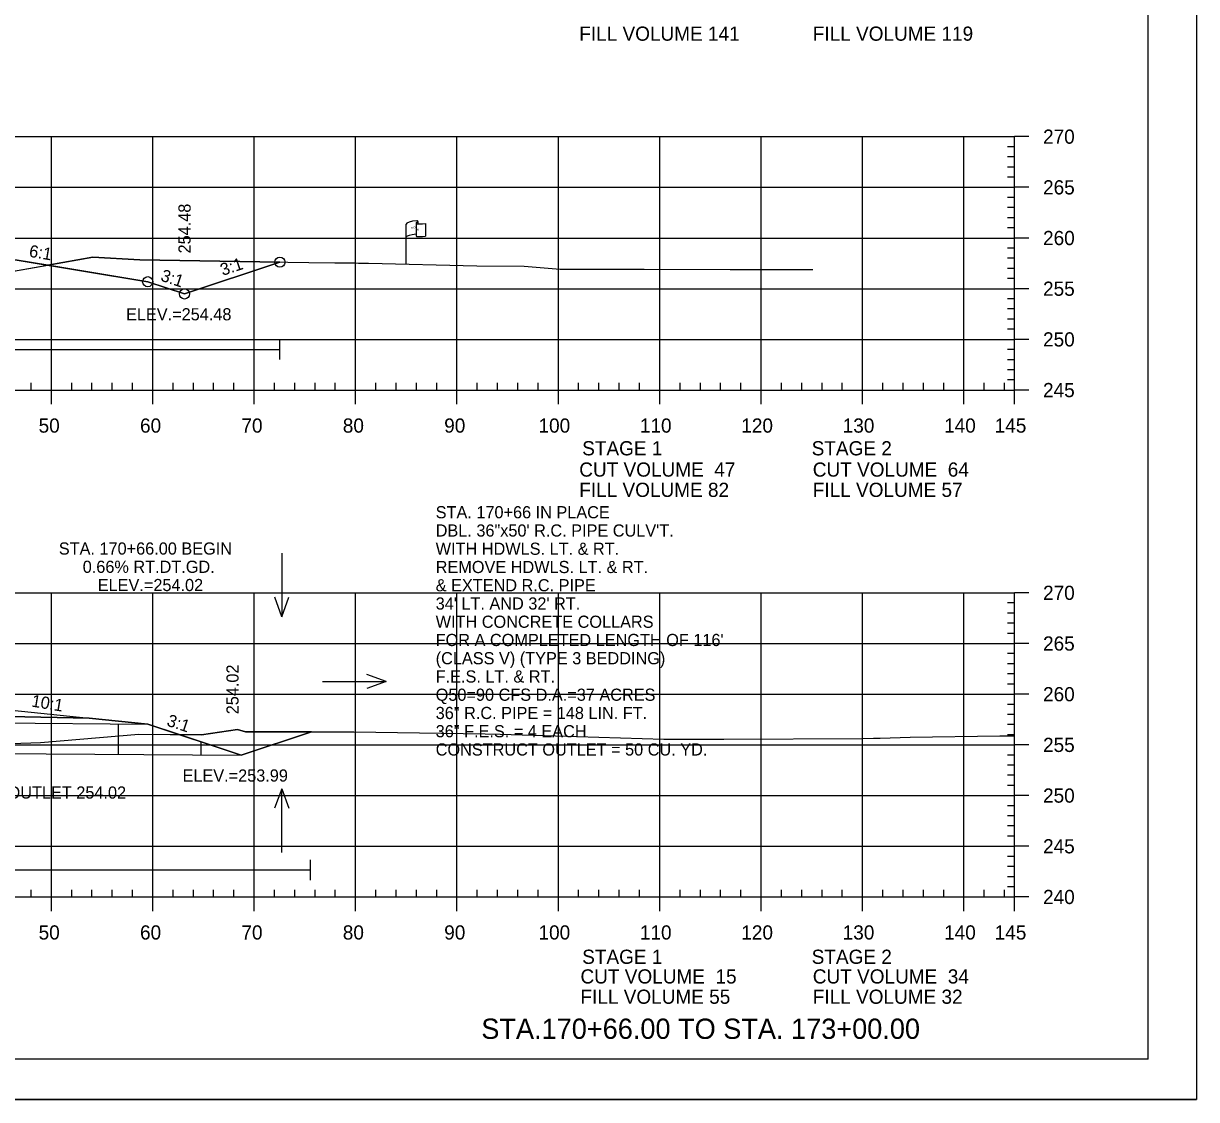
# Model space of a CAD drawing. Extents: x 1365647 to 1367999, y 387113 to 400173.
# Drawn here: x 1365941.3 to 1366057, y 387159.4 to 387265.5 of the extents above; entities that cross this region are included whole.
import ezdxf

# ---------------------------------------------------------------- set-up
doc = ezdxf.new("R2010")
doc.units = 0
for name, color, linetype in [('E_Existing ROW', 7, 'Continuous'), ('R_Alt Surface', 7, 'Continuous'), ('R_Axis', 7, 'Continuous'), ('R_Axis Annot', 7, 'Continuous'), ('R_Border', 7, 'Continuous'), ('R_Border Notes', 7, 'Continuous'), ('R_Contours', 7, 'Continuous'), ('R_Draft', 7, 'Continuous'), ('R_Exist Surface', 7, 'Continuous'), ('R_Fin Surface', 7, 'Continuous'), ('R_Fin Surface Annot', 7, 'Continuous'), ('R_Grid', 7, 'Continuous'), ('R_No Plot', 7, 'Continuous'), ('R_Proposed Const Limits', 7, 'Continuous'), ('R_Water', 7, 'Continuous'), ('R_Water Annot', 7, 'Continuous')]:
    doc.layers.add(name, color=color, linetype=linetype)

msp = doc.modelspace()

# ---------------------------------------------------------------- linework, layer by layer
at = {"layer": 'E_Existing ROW'}
for p, q in [((1365979.07, 387241.81), (1365979.07, 387245.76)), ((1365980.06, 387245.85), (1365980.06, 387245.84)), ((1365980.06, 387245.84), (1365980.06, 387244.61)), ((1365980.23, 387246.01), (1365980.23, 387245.77)), ((1365981, 387245.81), (1365981, 387244.57))]:
    msp.add_line(p, q, dxfattribs=at)
for centre, radius, start, end in [((1365980.14, 387245.85), 0.078, 88.6458, 274.2828), ((1365980.15, 387246.01), 0.0783, 263.0712, 93.9564), ((1365980.14, 387244.61), 0.0783, 180, 273.9564)]:
    msp.add_arc(centre, radius, start, end, dxfattribs=at)
for centre, major_axis, ratio, start_param, end_param in [((1365980.65, 387245.8), (-1.58, -0.04), 0.19887, 5.030368, 6.283185), ((1365981.36, 387245.91), (-1.23, -0.13), 0.052933, 0.159456, 1.268315), ((1365980.64, 387244.48), (-1.58, -0.04), 0.19887, 5.083035, 6.194897), ((1365981.36, 387244.67), (-1.23, -0.13), 0.052933, 0.159456, 1.268315)]:
    msp.add_ellipse(centre, major_axis=major_axis, ratio=ratio, start_param=start_param, end_param=end_param, dxfattribs=at)
at = {"layer": 'R_Alt Surface'}
msp.add_lwpolyline([(1365834.59, 387197.22), (1365862.59, 387197.47), (1365883.1, 387197.88), (1365883.1, 387199.17), (1365894.09, 387199.39), (1365906.38, 387199.14), (1365906.38, 387197.85), (1365925.59, 387197.47), (1365947.82, 387197.02)], dxfattribs=at)
at = {"layer": 'R_Axis'}
for p, q in [((1366039.09, 387253.38), (1366038.39, 387253.38)), ((1366039.09, 387229.38), (1366039.09, 387254.38)), ((1366040.49, 387254.38), (1366039.09, 387254.38)), ((1366039.09, 387252.38), (1366038.39, 387252.38)), ((1366039.09, 387251.38), (1366038.39, 387251.38)), ((1366039.09, 387250.38), (1366038.39, 387250.38)), ((1366040.49, 387249.38), (1366039.09, 387249.38)), ((1366039.09, 387248.38), (1366038.39, 387248.38)), ((1366039.09, 387247.38), (1366038.39, 387247.38)), ((1366039.09, 387246.38), (1366038.39, 387246.38)), ((1366039.09, 387245.38), (1366038.39, 387245.38)), ((1366040.49, 387244.38), (1366039.09, 387244.38)), ((1366039.09, 387243.38), (1366038.39, 387243.38)), ((1366039.09, 387242.38), (1366038.39, 387242.38)), ((1366039.09, 387241.38), (1366038.39, 387241.38)), ((1366039.09, 387240.38), (1366038.39, 387240.38)), ((1366039.09, 387238.38), (1366038.39, 387238.38)), ((1366040.49, 387239.38), (1366039.09, 387239.38)), ((1366039.09, 387237.38), (1366038.39, 387237.38)), ((1366039.09, 387236.38), (1366038.39, 387236.38)), ((1366039.09, 387235.38), (1366038.39, 387235.38)), ((1366040.49, 387234.38), (1366039.09, 387234.38)), ((1366039.09, 387233.38), (1366038.39, 387233.38)), ((1366039.09, 387232.38), (1366038.39, 387232.38)), ((1366039.09, 387231.38), (1366038.39, 387231.38)), ((1366039.09, 387230.38), (1366038.39, 387230.38)), ((1365749.09, 387229.38), (1366039.09, 387229.38)), ((1365942.09, 387229.38), (1365942.09, 387230.08)), ((1365944.09, 387227.98), (1365944.09, 387229.38)), ((1365946.09, 387229.38), (1365946.09, 387230.08)), ((1365948.09, 387229.38), (1365948.09, 387230.08)), ((1365950.09, 387229.38), (1365950.09, 387230.08)), ((1365952.09, 387229.38), (1365952.09, 387230.08)), ((1365954.09, 387227.98), (1365954.09, 387229.38)), ((1365956.09, 387229.38), (1365956.09, 387230.08)), ((1365958.09, 387229.38), (1365958.09, 387230.08)), ((1365960.09, 387229.38), (1365960.09, 387230.08)), ((1365962.09, 387229.38), (1365962.09, 387230.08)), ((1365964.09, 387227.98), (1365964.09, 387229.38)), ((1365966.09, 387229.38), (1365966.09, 387230.08)), ((1365968.09, 387229.38), (1365968.09, 387230.08)), ((1365970.09, 387229.38), (1365970.09, 387230.08)), ((1365972.09, 387229.38), (1365972.09, 387230.08)), ((1365974.09, 387227.98), (1365974.09, 387229.38)), ((1365976.09, 387229.38), (1365976.09, 387230.08)), ((1365978.09, 387229.38), (1365978.09, 387230.08)), ((1365980.09, 387229.38), (1365980.09, 387230.08)), ((1365982.09, 387229.38), (1365982.09, 387230.08)), ((1365984.09, 387227.98), (1365984.09, 387229.38)), ((1365986.09, 387229.38), (1365986.09, 387230.08)), ((1365988.09, 387229.38), (1365988.09, 387230.08)), ((1365990.09, 387229.38), (1365990.09, 387230.08)), ((1365992.09, 387229.38), (1365992.09, 387230.08)), ((1365994.09, 387227.98), (1365994.09, 387229.38)), ((1365996.09, 387229.38), (1365996.09, 387230.08)), ((1365998.09, 387229.38), (1365998.09, 387230.08)), ((1366000.09, 387229.38), (1366000.09, 387230.08)), ((1366002.09, 387229.38), (1366002.09, 387230.08)), ((1366004.09, 387227.98), (1366004.09, 387229.38)), ((1366006.09, 387229.38), (1366006.09, 387230.08)), ((1366008.09, 387229.38), (1366008.09, 387230.08)), ((1366010.09, 387229.38), (1366010.09, 387230.08)), ((1366012.09, 387229.38), (1366012.09, 387230.08)), ((1366014.09, 387227.98), (1366014.09, 387229.38)), ((1366016.09, 387229.38), (1366016.09, 387230.08)), ((1366018.09, 387229.38), (1366018.09, 387230.08)), ((1366020.09, 387229.38), (1366020.09, 387230.08)), ((1366022.09, 387229.38), (1366022.09, 387230.08)), ((1366024.09, 387227.98), (1366024.09, 387229.38)), ((1366026.09, 387229.38), (1366026.09, 387230.08)), ((1366028.09, 387229.38), (1366028.09, 387230.08)), ((1366030.09, 387229.38), (1366030.09, 387230.08)), ((1366032.09, 387229.38), (1366032.09, 387230.08)), ((1366034.09, 387227.98), (1366034.09, 387229.38)), ((1366036.09, 387229.38), (1366036.09, 387230.08)), ((1366038.09, 387229.38), (1366038.09, 387230.08)), ((1366039.09, 387227.98), (1366039.09, 387229.38)), ((1366040.49, 387229.38), (1366039.09, 387229.38)), ((1366039.09, 387208.38), (1366038.39, 387208.38)), ((1366039.09, 387179.38), (1366039.09, 387209.38)), ((1366040.49, 387209.38), (1366039.09, 387209.38)), ((1366039.09, 387207.38), (1366038.39, 387207.38)), ((1366039.09, 387206.38), (1366038.39, 387206.38)), ((1366039.09, 387205.38), (1366038.39, 387205.38)), ((1366040.49, 387204.38), (1366039.09, 387204.38)), ((1366039.09, 387203.38), (1366038.39, 387203.38)), ((1366039.09, 387202.38), (1366038.39, 387202.38)), ((1366039.09, 387201.38), (1366038.39, 387201.38)), ((1366039.09, 387200.38), (1366038.39, 387200.38)), ((1366040.49, 387199.38), (1366039.09, 387199.38)), ((1366039.09, 387198.38), (1366038.39, 387198.38)), ((1366039.09, 387197.38), (1366038.39, 387197.38)), ((1366039.09, 387196.38), (1366038.39, 387196.38)), ((1366039.09, 387195.38), (1366038.39, 387195.38)), ((1366040.49, 387194.38), (1366039.09, 387194.38)), ((1366039.09, 387193.38), (1366038.39, 387193.38)), ((1366039.09, 387192.38), (1366038.39, 387192.38)), ((1366039.09, 387191.38), (1366038.39, 387191.38)), ((1366039.09, 387190.38), (1366038.39, 387190.38)), ((1366040.49, 387189.38), (1366039.09, 387189.38)), ((1366039.09, 387188.38), (1366038.39, 387188.38)), ((1366039.09, 387187.38), (1366038.39, 387187.38)), ((1366039.09, 387186.38), (1366038.39, 387186.38)), ((1366039.09, 387185.38), (1366038.39, 387185.38)), ((1366040.49, 387184.38), (1366039.09, 387184.38)), ((1366039.09, 387183.38), (1366038.39, 387183.38)), ((1366039.09, 387182.38), (1366038.39, 387182.38)), ((1366039.09, 387181.38), (1366038.39, 387181.38)), ((1365749.09, 387179.38), (1366039.09, 387179.38)), ((1365942.09, 387179.38), (1365942.09, 387180.08)), ((1365944.09, 387177.98), (1365944.09, 387179.38)), ((1365946.09, 387179.38), (1365946.09, 387180.08)), ((1365948.09, 387179.38), (1365948.09, 387180.08)), ((1365950.09, 387179.38), (1365950.09, 387180.08)), ((1365952.09, 387179.38), (1365952.09, 387180.08)), ((1365954.09, 387177.98), (1365954.09, 387179.38)), ((1365956.09, 387179.38), (1365956.09, 387180.08)), ((1365958.09, 387179.38), (1365958.09, 387180.08)), ((1365960.09, 387179.38), (1365960.09, 387180.08)), ((1365962.09, 387179.38), (1365962.09, 387180.08)), ((1365964.09, 387177.98), (1365964.09, 387179.38)), ((1365966.09, 387179.38), (1365966.09, 387180.08)), ((1365968.09, 387179.38), (1365968.09, 387180.08)), ((1365970.09, 387179.38), (1365970.09, 387180.08)), ((1365972.09, 387179.38), (1365972.09, 387180.08)), ((1365974.09, 387177.98), (1365974.09, 387179.38)), ((1365976.09, 387179.38), (1365976.09, 387180.08)), ((1365978.09, 387179.38), (1365978.09, 387180.08)), ((1365980.09, 387179.38), (1365980.09, 387180.08)), ((1365982.09, 387179.38), (1365982.09, 387180.08)), ((1365984.09, 387177.98), (1365984.09, 387179.38)), ((1365986.09, 387179.38), (1365986.09, 387180.08)), ((1365988.09, 387179.38), (1365988.09, 387180.08)), ((1365990.09, 387179.38), (1365990.09, 387180.08)), ((1365992.09, 387179.38), (1365992.09, 387180.08)), ((1365994.09, 387177.98), (1365994.09, 387179.38)), ((1365996.09, 387179.38), (1365996.09, 387180.08)), ((1365998.09, 387179.38), (1365998.09, 387180.08)), ((1366000.09, 387179.38), (1366000.09, 387180.08)), ((1366002.09, 387179.38), (1366002.09, 387180.08)), ((1366004.09, 387177.98), (1366004.09, 387179.38)), ((1366006.09, 387179.38), (1366006.09, 387180.08)), ((1366008.09, 387179.38), (1366008.09, 387180.08)), ((1366010.09, 387179.38), (1366010.09, 387180.08)), ((1366012.09, 387179.38), (1366012.09, 387180.08)), ((1366014.09, 387177.98), (1366014.09, 387179.38)), ((1366016.09, 387179.38), (1366016.09, 387180.08)), ((1366018.09, 387179.38), (1366018.09, 387180.08)), ((1366020.09, 387179.38), (1366020.09, 387180.08)), ((1366022.09, 387179.38), (1366022.09, 387180.08)), ((1366024.09, 387177.98), (1366024.09, 387179.38)), ((1366026.09, 387179.38), (1366026.09, 387180.08)), ((1366028.09, 387179.38), (1366028.09, 387180.08)), ((1366030.09, 387179.38), (1366030.09, 387180.08)), ((1366032.09, 387179.38), (1366032.09, 387180.08)), ((1366034.09, 387177.98), (1366034.09, 387179.38)), ((1366036.09, 387179.38), (1366036.09, 387180.08)), ((1366038.09, 387179.38), (1366038.09, 387180.08)), ((1366039.09, 387180.38), (1366038.39, 387180.38)), ((1366039.09, 387177.98), (1366039.09, 387179.38)), ((1366040.49, 387179.38), (1366039.09, 387179.38))]:
    msp.add_line(p, q, dxfattribs=at)
at = {"layer": 'R_Border'}
for q in [(1366052.27, 387368.84), (1365736.09, 387163.38)]:
    msp.add_line((1366052.27, 387163.38), q, dxfattribs=at)
at = {"layer": 'R_Contours'}
for p, q in [((1365943.74, 387241.71), (1365953.59, 387240.07)), ((1365962.79, 387193.36), (1365969.74, 387195.68)), ((1365956.7, 387195.4), (1365962.79, 387193.36))]:
    msp.add_line(p, q, dxfattribs=at)
for points in [[(1365918.26, 387242.66), (1365921.8, 387241.75), (1365928.13, 387240.33), (1365930.06, 387239.89), (1365930.55, 387239.93), (1365936.05, 387240.24), (1365937.69, 387240.65), (1365943.74, 387241.71), (1365940.72, 387242.21), (1365925.59, 387242.52)], [(1365943.74, 387241.71), (1365948.16, 387242.49), (1365952.81, 387242.23), (1365966.63, 387242), (1365957.22, 387238.86), (1365953.59, 387240.07)], [(1365917.65, 387197.63), (1365918.43, 387197.36), (1365918.9, 387197.26), (1365919.65, 387197.14), (1365920.43, 387194.63), (1365920.89, 387193.95), (1365932.66, 387194.31), (1365937.2, 387194.43), (1365943.03, 387194.63), (1365952.7, 387195.43), (1365956.7, 387195.4), (1365953.59, 387196.43), (1365947.82, 387197.02), (1365925.59, 387197.47)], [(1365956.7, 387195.4), (1365958.9, 387195.38), (1365962.46, 387195.91), (1365963.22, 387195.68), (1365969.74, 387195.68), (1365962.79, 387193.36)]]:
    msp.add_lwpolyline(points, close=True, dxfattribs=at)
for points in [[(1365966.63, 387242), (1365952.81, 387242.23), (1365948.16, 387242.49), (1365943.74, 387241.71)], [(1365953.59, 387240.07), (1365957.22, 387238.86), (1365966.63, 387242)], [(1365969.74, 387195.68), (1365963.22, 387195.68), (1365962.46, 387195.91), (1365958.9, 387195.38), (1365956.7, 387195.4)]]:
    msp.add_lwpolyline(points, dxfattribs=at)
at = {"layer": 'R_Exist Surface'}
for points in [[(1365937.69, 387240.65), (1365948.16, 387242.49), (1365952.81, 387242.23), (1365969.49, 387241.95), (1365972.04, 387241.93), (1365973.98, 387241.93), (1365974.38, 387241.89), (1365975.37, 387241.89), (1365986.04, 387241.64), (1365990.71, 387241.61), (1365994.28, 387241.3), (1366002.55, 387241.32), (1366011.04, 387241.27), (1366019.17, 387241.29)], [(1365937.2, 387194.43), (1365943.03, 387194.63), (1365952.7, 387195.43), (1365958.9, 387195.38), (1365962.46, 387195.91), (1365963.22, 387195.68), (1365970.46, 387195.68), (1365973.92, 387195.68), (1365986.88, 387195.46), (1365988.34, 387195.45), (1365993.79, 387195.27), (1366004.5, 387194.93), (1366010.41, 387194.95), (1366024.12, 387195.02), (1366025.16, 387195.03), (1366025.83, 387195.05), (1366028.8, 387195.14), (1366037.64, 387195.28), (1366039.09, 387195.29)]]:
    msp.add_lwpolyline(points, dxfattribs=at)
at = {"layer": 'R_Fin Surface'}
for points in [[(1365823.26, 387242.8), (1365833.02, 387239.54), (1365834.59, 387240.07), (1365847.47, 387242.21), (1365856.59, 387243.73), (1365862.59, 387243.97), (1365864.59, 387244.01), (1365894.09, 387244.6), (1365923.59, 387244.01), (1365925.59, 387243.97), (1365931.59, 387243.73), (1365940.72, 387242.21), (1365953.59, 387240.07), (1365957.22, 387238.86), (1365966.63, 387242)], [(1365815.46, 387197.88), (1365826.02, 387194.36), (1365830.31, 387195.79), (1365834.59, 387197.22), (1365856.59, 387198.69), (1365862.59, 387198.93), (1365864.59, 387198.97), (1365894.09, 387199.56), (1365923.59, 387198.97), (1365925.59, 387198.93), (1365931.59, 387198.69), (1365947.82, 387197.02), (1365953.59, 387196.43), (1365962.79, 387193.36), (1365969.74, 387195.68)]]:
    msp.add_lwpolyline(points, dxfattribs=at)
at = {"layer": 'R_Grid'}
for p, q in [((1365749.09, 387254.38), (1366039.09, 387254.38)), ((1365944.09, 387229.38), (1365944.09, 387254.38)), ((1365954.09, 387229.38), (1365954.09, 387254.38)), ((1365964.09, 387229.38), (1365964.09, 387254.38)), ((1365974.09, 387229.38), (1365974.09, 387254.38)), ((1365984.09, 387229.38), (1365984.09, 387254.38)), ((1365994.09, 387229.38), (1365994.09, 387254.38)), ((1366004.09, 387229.38), (1366004.09, 387254.38)), ((1366014.09, 387229.38), (1366014.09, 387254.38)), ((1366024.09, 387229.38), (1366024.09, 387254.38)), ((1366034.09, 387229.38), (1366034.09, 387254.38)), ((1366039.09, 387229.38), (1366039.09, 387254.38)), ((1365749.09, 387249.38), (1366039.09, 387249.38)), ((1365749.09, 387244.38), (1366039.09, 387244.38)), ((1365749.09, 387239.38), (1366039.09, 387239.38)), ((1365749.09, 387234.38), (1366039.09, 387234.38)), ((1365749.09, 387229.38), (1366039.09, 387229.38)), ((1365749.09, 387209.38), (1366039.09, 387209.38)), ((1365944.09, 387179.38), (1365944.09, 387209.38)), ((1365954.09, 387179.38), (1365954.09, 387209.38)), ((1365964.09, 387179.38), (1365964.09, 387209.38)), ((1365974.09, 387179.38), (1365974.09, 387209.38)), ((1365984.09, 387179.38), (1365984.09, 387209.38)), ((1365994.09, 387179.38), (1365994.09, 387209.38)), ((1366004.09, 387179.38), (1366004.09, 387209.38)), ((1366014.09, 387179.38), (1366014.09, 387209.38)), ((1366024.09, 387179.38), (1366024.09, 387209.38)), ((1366034.09, 387179.38), (1366034.09, 387209.38)), ((1366039.09, 387179.38), (1366039.09, 387209.38)), ((1365749.09, 387204.38), (1366039.09, 387204.38)), ((1365749.09, 387199.38), (1366039.09, 387199.38)), ((1365749.09, 387194.38), (1366039.09, 387194.38)), ((1365749.09, 387189.38), (1366039.09, 387189.38)), ((1365749.09, 387184.38), (1366039.09, 387184.38)), ((1365749.09, 387179.38), (1366039.09, 387179.38))]:
    msp.add_line(p, q, dxfattribs=at)
at = {"layer": 'R_No Plot'}
msp.add_line((1365723.69, 387159.4), (1366057.03, 387159.4), dxfattribs=at)
msp.add_lwpolyline([(1365723.69, 387372.73), (1366057.03, 387372.73), (1366057.03, 387159.4), (1365723.69, 387159.4)], close=True, dxfattribs=at)
for centre in [(1365966.63, 387242), (1365966.63, 387242), (1365953.59, 387240.07), (1365953.59, 387240.07), (1365953.59, 387240.07), (1365953.59, 387240.07), (1365953.59, 387240.07), (1365957.22, 387238.86), (1365957.22, 387238.86), (1365957.22, 387238.86), (1365957.22, 387238.86), (1365957.22, 387238.86)]:
    msp.add_circle(centre, 0.5, dxfattribs=at)
at = {"layer": 'R_Proposed Const Limits'}
msp.add_lwpolyline([(1365957.22, 387238.86), (1365966.63, 387242)], dxfattribs=at)
at = {"layer": 'R_Water'}
for p, q in [((1365966.63, 387232.39), (1365966.63, 387234.39)), ((1365883.11, 387233.39), (1365966.63, 387233.39)), ((1365919.86, 387196.68), (1365953.59, 387196.43)), ((1365950.69, 387196.45), (1365950.69, 387193.45)), ((1365958.83, 387194.68), (1365958.83, 387193.39)), ((1365919.83, 387193.68), (1365962.79, 387193.36)), ((1365969.65, 387181.05), (1365969.65, 387183.05)), ((1365883.1, 387182.05), (1365969.65, 387182.05))]:
    msp.add_line(p, q, dxfattribs=at)
at = {"layer": 'R_Water Annot'}
for p, q in [((1365966.81, 387213.3), (1365966.81, 387207.02)), ((1365966.81, 387207.02), (1365966.11, 387208.94)), ((1365966.81, 387207.02), (1365967.51, 387208.94)), ((1365977.12, 387200.64), (1365975.2, 387201.34)), ((1365970.84, 387200.64), (1365977.12, 387200.64)), ((1365977.12, 387200.64), (1365975.2, 387199.94)), ((1365966.8, 387190.06), (1365966.1, 387188.13)), ((1365966.8, 387183.77), (1365966.8, 387190.06)), ((1365966.8, 387190.06), (1365967.5, 387188.13))]:
    msp.add_line(p, q, dxfattribs=at)

# ---------------------------------------------------------------- texts
at = {"layer": 'E_Existing ROW'}
for s, height, rotation, p in [('R ', 0.2, 9.9884, (1365979.59, 387245.26)), (' O', 0.2, 9.9884, (1365979.73, 387245.3)), ('W', 0.2, 351.1788, (1365980.06, 387245.13)), ('DWB 11-9-07', 0.001, 90, (1365980.23, 387245.77)), ('DWB 11-9-07', 0.001, 5.0717, (1365980.99, 387244.57)), ('DWB 11-9-07', 0.001, 90, (1365979.07, 387241.81))]:
    msp.add_text(s, height=height, rotation=rotation, dxfattribs=at).set_placement(p)
at = {"layer": 'R_Axis Annot'}
for s, p in [('FILL VOLUME 141', (1365996.15, 387263.84)), ('FILL VOLUME 119', (1366019.18, 387263.84)), ('270', (1366041.89, 387253.68)), ('265', (1366041.89, 387248.68)), ('260', (1366041.89, 387243.68)), ('255', (1366041.89, 387238.68)), ('250', (1366041.89, 387233.68)), ('245', (1366041.89, 387228.68)), ('50', (1365942.83, 387225.18)), ('60', (1365952.83, 387225.18)), ('70', (1365962.83, 387225.18)), ('80', (1365972.83, 387225.18)), ('90', (1365982.83, 387225.18)), ('100', (1365992.13, 387225.18)), ('110', (1366002.13, 387225.18)), ('120', (1366012.13, 387225.18)), ('130', (1366022.13, 387225.18)), ('140', (1366032.13, 387225.18)), ('145', (1366037.12, 387225.18)), ('STAGE 1', (1365996.44, 387222.94)), ('STAGE 2', (1366019.07, 387222.94)), ('CUT VOLUME  47', (1365996.15, 387220.84)), ('CUT VOLUME  64', (1366019.18, 387220.84)), ('FILL VOLUME 82', (1365996.15, 387218.84)), ('FILL VOLUME 57', (1366019.18, 387218.84)), ('270', (1366041.89, 387208.68)), ('265', (1366041.89, 387203.68)), ('260', (1366041.89, 387198.68)), ('255', (1366041.89, 387193.68)), ('250', (1366041.89, 387188.68)), ('245', (1366041.89, 387183.68)), ('240', (1366041.89, 387178.68)), ('50', (1365942.83, 387175.18)), ('60', (1365952.83, 387175.18)), ('70', (1365962.83, 387175.18)), ('80', (1365972.83, 387175.18)), ('90', (1365982.83, 387175.18)), ('100', (1365992.13, 387175.18)), ('110', (1366002.13, 387175.18)), ('120', (1366012.13, 387175.18)), ('130', (1366022.13, 387175.18)), ('140', (1366032.13, 387175.18)), ('145', (1366037.12, 387175.18)), ('STAGE 1', (1365996.44, 387172.78)), ('STAGE 2', (1366019.07, 387172.78)), ('CUT VOLUME  15', (1365996.27, 387170.84)), ('CUT VOLUME  34', (1366019.18, 387170.84)), ('FILL VOLUME 55', (1365996.27, 387168.84)), ('FILL VOLUME 32', (1366019.18, 387168.84))]:
    msp.add_text(s, height=1.4, dxfattribs=at).set_placement(p)
at = {"layer": 'R_Border Notes'}
for s, p in [('ELEV.=254.48', (1365951.45, 387236.26)), ('ELEV.=253.99', (1365957.02, 387190.76))]:
    msp.add_text(s, height=1.2, dxfattribs=at).set_placement(p)
at = {"layer": 'R_Draft'}
for s, p in [('STA. 170+66 IN PLACE', (1365981.99, 387216.73)), ('DBL. 36"x50\' R.C. PIPE CULV\'T.', (1365981.99, 387214.93)), ('WITH HDWLS. LT. & RT.', (1365981.99, 387213.13)), ('REMOVE HDWLS. LT. & RT. ', (1365981.99, 387211.33)), ('& EXTEND R.C. PIPE', (1365981.99, 387209.53)), ("34' LT. AND 32' RT.", (1365981.99, 387207.73)), ('WITH CONCRETE COLLARS', (1365981.99, 387205.93)), ("FOR A COMPLETED LENGTH OF 116'", (1365981.99, 387204.13)), ('(CLASS V) (TYPE 3 BEDDING) ', (1365981.99, 387202.33)), ('F.E.S. LT. & RT.', (1365981.99, 387200.53)), ('Q50=90 CFS D.A.=37 ACRES', (1365981.99, 387198.73)), ('36" R.C. PIPE = 148 LIN. FT.', (1365981.99, 387196.93)), ('36" F.E.S. = 4 EACH ', (1365981.99, 387195.13)), ('CONSTRUCT OUTLET = 50 CU. YD.', (1365981.99, 387193.33))]:
    msp.add_text(s, height=1.2, rotation=360, dxfattribs=at).set_placement(p)
msp.add_text('STA.170+66.00 TO STA. 173+00.00', height=2, dxfattribs=at).set_placement((1365986.49, 387165.38))
at = {"layer": 'R_Fin Surface Annot'}
for s, rotation, p in [('254.48', 90, (1365957.82, 387242.86)), ('6:1', 350.5377, (1365941.83, 387242.54)), ('6:1', 350.5369, (1365941.83, 387242.54)), ('3:1', 18.4349, (1365960.98, 387240.64)), ('3:1', 18.4341, (1365960.98, 387240.64)), ('3:1', 341.5651, (1365954.78, 387240.2)), ('3:1', 341.562, (1365954.78, 387240.2)), ('254.02', 90, (1365962.55, 387197.4)), ('10:1', 350.5377, (1365942.07, 387198.17)), ('3:1', 341.5651, (1365955.39, 387196.3))]:
    msp.add_text(s, height=1.2, rotation=rotation, dxfattribs=at).set_placement(p)
at = {"layer": 'R_Water'}
for s, p in [('STA. 170+66.00 BEGIN', (1365944.82, 387213.15)), ('0.66% RT.DT.GD.', (1365947.18, 387211.35)), ('ELEV.=254.02', (1365948.66, 387209.55)), ('F.L. OUTLET 254.02', (1365936.56, 387189.08))]:
    msp.add_text(s, height=1.2, dxfattribs=at).set_placement(p)

doc.saveas('drawing.dxf')
